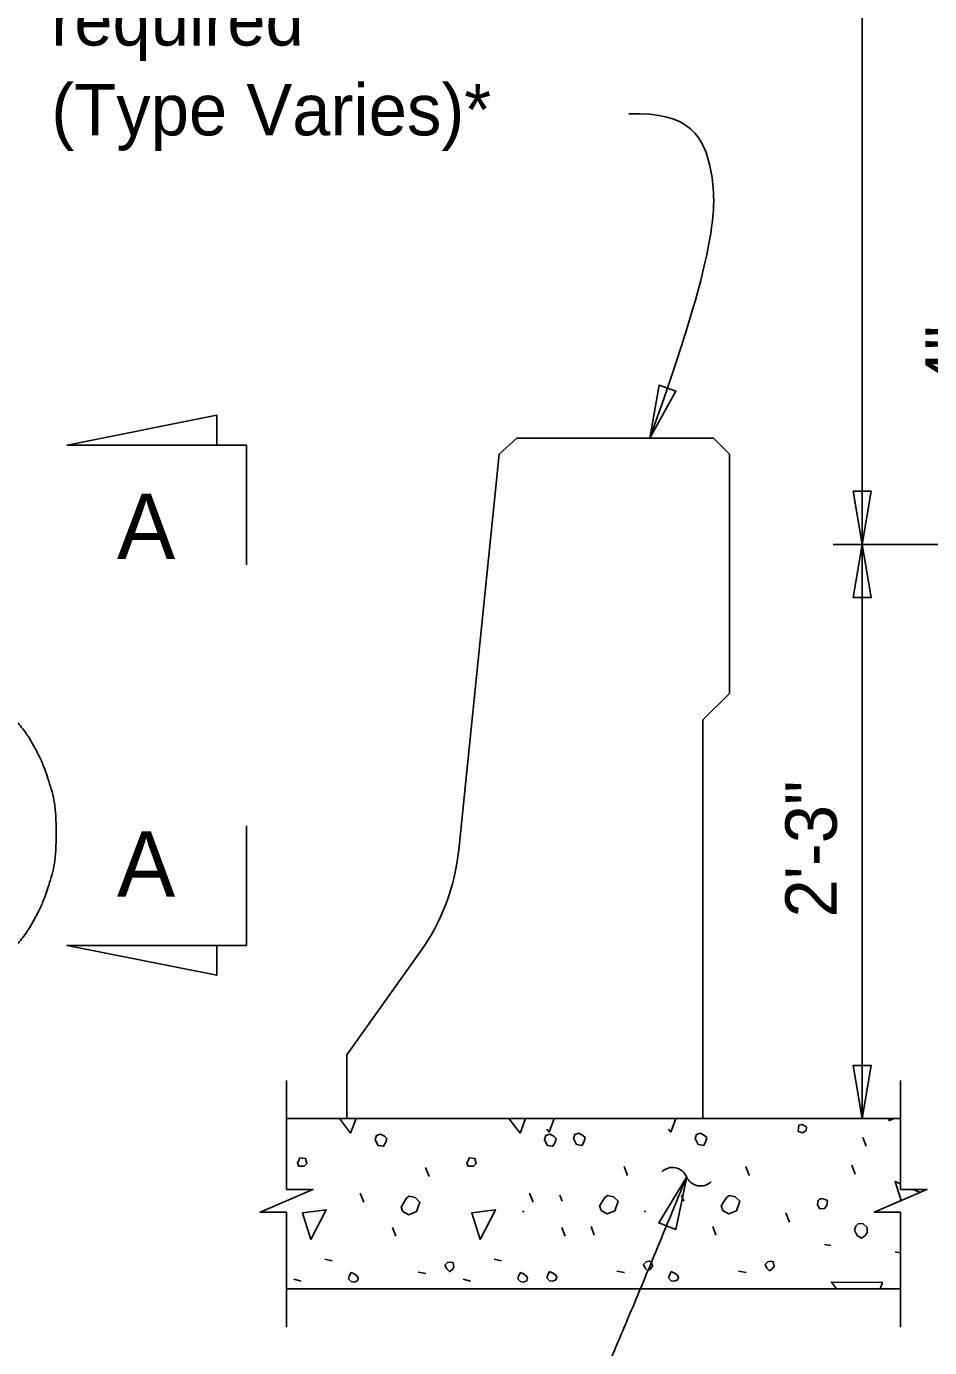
# Model space of a CAD drawing. Extents: x 0 to 41.1, y 0 to 25.9.
# Drawn here: x 33.7 to 37.24, y 13.66 to 18.84 of the extents above; entities that cross this region are included whole.
import ezdxf

# ---------------------------------------------------------------- set-up
doc = ezdxf.new("R2010")
doc.units = 0
for name, color, linetype in [('Dimension', 7, 'Continuous'), ('Miscellaneous', 7, 'Continuous'), ('SupstrConc', 7, 'Continuous'), ('SupstrConc_h', 7, 'Continuous'), ('TextStructures', 7, 'Continuous')]:
    doc.layers.add(name, color=color, linetype=linetype)

# ---------------------------------------------------------------- blocks, each defined once
blk = doc.blocks.new('Terminator-Arrow')
at = {"layer": 'Dimension'}
blk.add_lwpolyline([(0, 0), (-0.00041, 0.000069), (-0.00041, -0.000069), (0, 0)], dxfattribs=at)
blk.add_lwpolyline([(0, 0), (-0.00041, 0.000069), (-0.00041, -0.000069)], close=True, dxfattribs=at)

msp = doc.modelspace()

# ---------------------------------------------------------------- linework, layer by layer
at = {"layer": 'Dimension'}
for p, q in [((36.9797, 14.5781), (36.9797, 22.8079)), ((33.8643, 17.1974), (34.4503, 17.3146)), ((34.4503, 17.3146), (34.4503, 17.1974)), ((34.5675, 17.1974), (33.8643, 17.1974)), ((34.5675, 16.7286), (34.5675, 17.1974)), ((39.5643, 16.8079), (36.8659, 16.8079)), ((34.5675, 15.7056), (34.5675, 15.2368)), ((34.5675, 15.2368), (33.8643, 15.2368)), ((33.8643, 15.2368), (34.4503, 15.1196)), ((34.4503, 15.1196), (34.4503, 15.2368))]:
    msp.add_line(p, q, dxfattribs=at)
for points in [[(34.4503, 17.1974), (34.4503, 17.3146), (33.8643, 17.1974)], [(36.9797, 16.8079), (36.9444, 17.0162), (37.015, 17.0162)], [(36.9797, 16.8079), (36.9444, 16.5997), (37.015, 16.5997)], [(34.4503, 15.2368), (34.4503, 15.1196), (33.8643, 15.2368)], [(36.9797, 14.5579), (37.015, 14.7662), (36.9444, 14.7662)], [(36.2916, 14.3302), (36.1831, 14.149), (36.2488, 14.1234)]]:
    msp.add_lwpolyline(points, close=True, dxfattribs=at)
for points in [[(34.7238, 14.7079), (34.7238, 14.2808), (34.8272, 14.2808), (34.7238, 14.2358), (34.6205, 14.1908), (34.7238, 14.1908), (34.7238, 13.7412)], [(37.1296, 14.7079), (37.1296, 14.2808), (37.233, 14.2808), (37.1296, 14.2358), (37.0263, 14.1908), (37.1296, 14.1908), (37.1296, 13.7412)]]:
    msp.add_lwpolyline(points, dxfattribs=at)
for centre, start, end in [((36.236, 14.3072), 22.8801, 134.6073), ((36.3458, 14.3536), 202.8801, 314.6073)]:
    msp.add_arc(centre, 0.0596, start, end, dxfattribs=at)
for points, degree in [([(36.0647, 18.496), (36.3066, 18.5019), (36.4128, 18.3129), (36.4128, 17.9586), (36.1473, 17.2245)], 3), ([(33.2986, 15.0608), (33.3336, 15.0608), (33.3683, 15.0649), (33.4362, 15.0811), (33.4694, 15.0931), (33.5172, 15.1167), (33.5328, 15.1255), (33.5556, 15.14), (33.5631, 15.1451), (33.5779, 15.1557), (33.5851, 15.1612), (33.6208, 15.1896), (33.6471, 15.2155), (33.695, 15.2726), (33.7165, 15.3038), (33.7399, 15.3457), (33.7444, 15.3542), (33.7531, 15.3715), (33.7573, 15.3803), (33.7692, 15.4069), (33.7764, 15.4251), (33.8084, 15.5175), (33.8217, 15.5966), (33.8217, 15.7569), (33.8084, 15.836), (33.7764, 15.9283), (33.7692, 15.9465), (33.7573, 15.9731), (33.7531, 15.9819), (33.7444, 15.9992), (33.7399, 16.0077), (33.7165, 16.0496), (33.695, 16.0808), (33.6471, 16.138), (33.6208, 16.1638), (33.5851, 16.1923), (33.5779, 16.1978), (33.5631, 16.2083), (33.5556, 16.2134), (33.5328, 16.2279), (33.5172, 16.2367), (33.4694, 16.2603), (33.4362, 16.2724), (33.3683, 16.2885), (33.3336, 16.2926), (33.2636, 16.2926), (33.2289, 16.2885), (33.1609, 16.2724), (33.1278, 16.2603), (33.08, 16.2367), (33.0644, 16.2279), (33.0416, 16.2134), (33.0341, 16.2083), (33.0193, 16.1978), (33.0121, 16.1923), (32.9764, 16.1638), (32.9501, 16.138), (32.9022, 16.0808), (32.8807, 16.0496), (32.8573, 16.0077), (32.8527, 15.9992), (32.8441, 15.9819), (32.8399, 15.9731), (32.828, 15.9465), (32.8208, 15.9283), (32.7887, 15.836), (32.7755, 15.7569), (32.7755, 15.5966), (32.7887, 15.5175), (32.8208, 15.4251), (32.828, 15.4069), (32.8399, 15.3803), (32.8441, 15.3715), (32.8527, 15.3542), (32.8573, 15.3457), (32.8807, 15.3038), (32.9022, 15.2726), (32.9501, 15.2155), (32.9764, 15.1896), (33.0121, 15.1612), (33.0193, 15.1557), (33.0341, 15.1451), (33.0416, 15.14), (33.0644, 15.1255), (33.08, 15.1167), (33.1278, 15.0931), (33.1609, 15.0811), (33.2289, 15.0649), (33.2636, 15.0608), (33.2986, 15.0608)], 3), ([(36.2826, 13.2929), (36.0506, 13.2762), (35.9147, 13.4352), (36.0652, 13.7784), (36.2916, 14.3302)], 2)]:
    msp.add_open_spline(points, degree=degree, dxfattribs=at)
at = {"layer": 'Miscellaneous'}
for p, q in [((35.3909, 14.5579), (35.3923, 14.5576)), ((36.9947, 14.4498), (36.9824, 14.4834)), ((35.2827, 14.3313), (35.2685, 14.3667)), ((36.0602, 14.3349), (36.0461, 14.3702)), ((36.5369, 14.3349), (36.5228, 14.3702)), ((36.9523, 14.3402), (36.9382, 14.3755)), ((35.0263, 14.2306), (35.0122, 14.2659)), ((35.6898, 14.2306), (35.6757, 14.2659)), ((35.8039, 14.2341), (35.7944, 14.2578)), ((36.2806, 14.2341), (36.2711, 14.2578)), ((36.6942, 14.1528), (36.6801, 14.1882)), ((35.9294, 14.1015), (35.917, 14.1351)), ((36.4061, 14.1015), (36.3937, 14.1351)), ((35.1519, 14.098), (35.1395, 14.1316)), ((35.8154, 14.098), (35.803, 14.1316)), ((36.8321, 14.0644), (36.8569, 14.0609)), ((37.1079, 14.0361), (37.1296, 14.0323)), ((34.8743, 14.0078), (34.9026, 14.0008)), ((35.5378, 14.0078), (35.5661, 14.0008)), ((34.7523, 13.9283), (34.7806, 13.9212)), ((35.2402, 13.9566), (35.2703, 13.9513)), ((35.4158, 13.9283), (35.4441, 13.9212)), ((36.0178, 13.9601), (36.0478, 13.9548)), ((36.4945, 13.9601), (36.5245, 13.9548))]:
    msp.add_line(p, q, dxfattribs=at)
for points in [[(34.9751, 14.501), (34.9319, 14.5579)], [(34.9963, 14.5579), (34.9751, 14.501)], [(35.6386, 14.501), (35.5954, 14.5579)], [(35.6598, 14.5579), (35.6386, 14.501)], [(35.7725, 14.5579), (35.7526, 14.5046)], [(36.2492, 14.5579), (36.2293, 14.5046)], [(37.0831, 14.5488), (37.0859, 14.5579)], [(37.1034, 14.5579), (37.0831, 14.5488)], [(35.0741, 14.4692), (35.0829, 14.4533), (35.1041, 14.4498), (35.113, 14.4657), (35.1165, 14.4798), (35.1077, 14.4887), (35.0918, 14.4975), (35.0758, 14.4922), (35.0705, 14.4763), (35.0741, 14.4692)], [(35.7376, 14.4692), (35.7464, 14.4533), (35.7676, 14.4498), (35.7765, 14.4657), (35.78, 14.4798), (35.7712, 14.4887), (35.7553, 14.4975), (35.7393, 14.4922), (35.734, 14.4763), (35.7376, 14.4692)], [(35.7526, 14.5046), (35.7438, 14.5162)], [(35.8516, 14.4728), (35.8605, 14.4569), (35.8817, 14.4533), (35.8905, 14.4692), (35.894, 14.4834), (35.8852, 14.4922), (35.8693, 14.501), (35.8534, 14.4957), (35.8481, 14.4798), (35.8516, 14.4728)], [(36.2293, 14.5046), (36.2205, 14.5162)], [(36.3283, 14.4728), (36.3371, 14.4569), (36.3584, 14.4533), (36.3672, 14.4692), (36.3707, 14.4834), (36.3619, 14.4922), (36.346, 14.501), (36.3301, 14.4957), (36.3248, 14.4798), (36.3283, 14.4728)], [(36.7278, 14.5081), (36.7473, 14.5028), (36.7596, 14.5117), (36.7614, 14.524), (36.7579, 14.5276), (36.7437, 14.5346), (36.7314, 14.5329), (36.7296, 14.5205), (36.7278, 14.5081)], [(34.7718, 14.372), (34.793, 14.372), (34.8036, 14.3826), (34.7983, 14.4021), (34.7753, 14.4038), (34.7718, 14.3932), (34.7665, 14.3844), (34.7718, 14.372), (34.7683, 14.3755)], [(35.4353, 14.372), (35.4565, 14.372), (35.4671, 14.3826), (35.4618, 14.4021), (35.4388, 14.4038), (35.4353, 14.3932), (35.43, 14.3844), (35.4353, 14.372), (35.4318, 14.3755)], [(37.1323, 14.2369), (37.1079, 14.3119), (37.1296, 14.3024)], [(35.1801, 14.1935), (35.2031, 14.1811), (35.2332, 14.1935), (35.2455, 14.2306), (35.2279, 14.2483), (35.2049, 14.2536), (35.1943, 14.2465), (35.1819, 14.227), (35.1731, 14.2111), (35.1801, 14.1935)], [(35.9577, 14.197), (35.9807, 14.1846), (36.0107, 14.197), (36.0231, 14.2341), (36.0054, 14.2518), (35.9824, 14.2571), (35.9718, 14.25), (35.9594, 14.2306), (35.9506, 14.2147), (35.9577, 14.197)], [(36.4344, 14.197), (36.4573, 14.1846), (36.4874, 14.197), (36.4998, 14.2341), (36.4821, 14.2518), (36.4591, 14.2571), (36.4485, 14.25), (36.4361, 14.2306), (36.4273, 14.2147), (36.4344, 14.197)], [(36.8038, 14.22), (36.8127, 14.2041), (36.8321, 14.2058), (36.841, 14.2182), (36.8427, 14.2377), (36.8303, 14.243), (36.8215, 14.2447), (36.8109, 14.2412), (36.8074, 14.2377), (36.8038, 14.22)], [(37.1792, 14.2808), (37.206, 14.269)], [(34.8195, 14.0839), (34.7859, 14.1882), (34.8796, 14.2005), (34.8195, 14.0839)], [(35.483, 14.0839), (35.4494, 14.1882), (35.5431, 14.2005), (35.483, 14.0839)], [(35.6532, 14.1963), (35.6503, 14.1908)], [(36.1298, 14.1963), (36.127, 14.1908)], [(36.9488, 14.121), (36.9594, 14.0998), (36.9771, 14.0892), (36.9912, 14.0998), (36.9983, 14.1104), (36.9983, 14.1316), (36.9824, 14.1475), (36.9629, 14.1457), (36.9541, 14.1369), (36.9488, 14.121)], [(35.3516, 13.969), (35.3622, 13.9583), (35.3728, 13.9654), (35.3799, 13.976), (35.3764, 13.9937), (35.3675, 13.9955), (35.3551, 13.9937), (35.3445, 13.9831), (35.3516, 13.969)], [(36.1292, 13.9725), (36.1398, 13.9619), (36.1504, 13.969), (36.1574, 13.9796), (36.1539, 13.9972), (36.1451, 13.999), (36.1327, 13.9972), (36.1221, 13.9866), (36.1292, 13.9725)], [(36.6058, 13.9725), (36.6164, 13.9619), (36.6271, 13.969), (36.6341, 13.9796), (36.6306, 13.9972), (36.6218, 13.999), (36.6094, 13.9972), (36.5988, 13.9866), (36.6058, 13.9725)], [(34.9768, 13.9195), (34.9892, 13.9177), (35.0016, 13.923), (35.0051, 13.9336), (34.9998, 13.9424), (34.9892, 13.9495), (34.9768, 13.9548), (34.9698, 13.9407), (34.9662, 13.9301), (34.9768, 13.9195)], [(35.6403, 13.9195), (35.6527, 13.9177), (35.6651, 13.923), (35.6686, 13.9336), (35.6633, 13.9424), (35.6527, 13.9495), (35.6403, 13.9548), (35.6333, 13.9407), (35.6297, 13.9301), (35.6403, 13.9195)], [(35.7544, 13.923), (35.7668, 13.9212), (35.7791, 13.9265), (35.7827, 13.9371), (35.7774, 13.946), (35.7668, 13.953), (35.7544, 13.9583), (35.7473, 13.9442), (35.7438, 13.9336)], [(35.7438, 13.9336), (35.7544, 13.923)], [(36.2311, 13.923), (36.2434, 13.9212), (36.2558, 13.9265), (36.2594, 13.9371), (36.2541, 13.946), (36.2434, 13.953), (36.2311, 13.9583), (36.224, 13.9442), (36.2205, 13.9336)], [(36.2205, 13.9336), (36.2311, 13.923)], [(36.8788, 13.8912), (36.8586, 13.9177), (37.0584, 13.9159), (37.0491, 13.8912)]]:
    msp.add_lwpolyline(points, dxfattribs=at)
at = {"layer": 'SupstrConc'}
msp.add_line((34.7238, 14.5579), (37.1296, 14.5579), dxfattribs=at)
at = {"layer": 'SupstrConc_h'}
for p, q in [((35.5573, 17.1623), (35.6261, 17.2245)), ((35.6262, 17.2246), (36.397, 17.2246)), ((36.397, 17.2245), (36.4595, 17.162)), ((35.3986, 15.611), (35.5573, 17.1623)), ((36.4595, 17.162), (36.4595, 16.2245)), ((36.4595, 16.2245), (36.3553, 16.1203)), ((36.3553, 16.1203), (36.3553, 14.5579)), ((34.9595, 14.8079), (35.2477, 15.2114)), ((34.9595, 14.5579), (34.9595, 14.8079)), ((37.1296, 13.8912), (34.7238, 13.8912))]:
    msp.add_line(p, q, dxfattribs=at)
msp.add_arc((34.5696, 15.6956), 0.8333, 324.4623, 354.1603, dxfattribs=at)

# ---------------------------------------------------------------- block references
at = {"layer": 'Dimension', "xscale": 507.9999699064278, "yscale": -507.99996990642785, "rotation": -109.44616743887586}
msp.add_blockref('Terminator-Arrow', (36.1473, 17.2245), dxfattribs=at)

# ---------------------------------------------------------------- texts
at = {"layer": 'Dimension'}
for s, p in [('required', (33.8024, 18.763)), ('(Type Varies)*', (33.8024, 18.411))]:
    msp.add_text(s, height=0.2016, dxfattribs=at).set_placement(p)
at = {"layer": 'TextStructures'}
for s, p in [('4"', (37.4279, 17.4197)), ('2\'-3"', (36.8797, 15.346))]:
    msp.add_text(s, height=0.2016, rotation=90, dxfattribs=at).set_placement(p)
for p in [(34.0596, 16.7507), (34.0596, 15.4277)]:
    msp.add_text('A', height=0.256, dxfattribs=at).set_placement(p)

doc.saveas('drawing.dxf')
